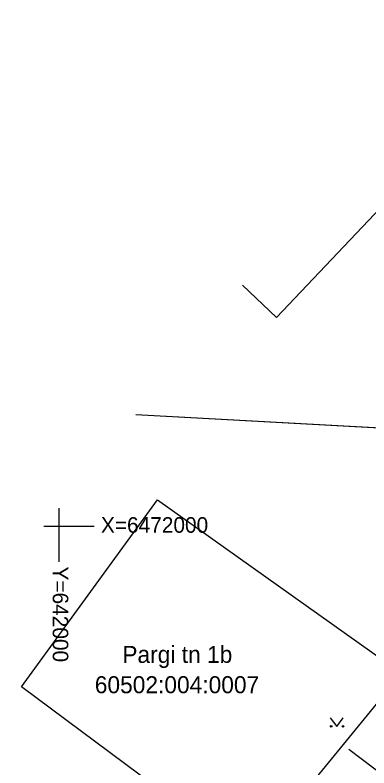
# Model space of a CAD drawing. Extents: x 641898 to 642452, y 6471715 to 6472255.
# Drawn here: x 641996.9 to 642021.9, y 6471983 to 6472036.1 of the extents above; entities that cross this region are included whole.
import ezdxf

# ---------------------------------------------------------------- set-up
doc = ezdxf.new("R2010")
doc.units = 0
for name, color, linetype in [('HALJASTUS', 7, 'Continuous'), ('HOONE', 7, 'Continuous'), ('MOOTPIIR', 7, 'Continuous'), ('MPOHULIIN', 7, 'Continuous'), ('PIIR', 7, 'Continuous'), ('SIOHULIIN', 7, 'Continuous'), ('VORK', 7, 'Continuous')]:
    doc.layers.add(name, color=color, linetype=linetype)

msp = doc.modelspace()

# ---------------------------------------------------------------- linework, layer by layer
at = {"layer": 'HALJASTUS'}
for p, q in [((642019.157, 6471986.488), (642019.621, 6471985.882)), ((642019.621, 6471985.882), (642020.066, 6471986.488))]:
    msp.add_line(p, q, dxfattribs=at)
for centre in [(642019.22, 6471985.882), (642020.049, 6471985.882)]:
    msp.add_circle(centre, 0.055, dxfattribs=at)
at = {"layer": 'HOONE'}
msp.add_lwpolyline([(642020.456, 6471984.276), (642023.066, 6471982.309), (642019.558, 6471977.655), (642016.948, 6471979.622)], dxfattribs=at)
at = {"layer": 'MOOTPIIR'}
msp.add_lwpolyline([(642057.038, 6472006.154), (641981.622, 6471911.832), (641974.173, 6471900.785), (641991.385, 6471889.279), (641976.334, 6471874.678), (641962.442, 6471882.56), (641955.727, 6471896.847), (641967.922, 6471920.935), (642044.157, 6472013.993), (642057.02, 6472034.672), (642071.202, 6472024.941)], close=True, dxfattribs=at)
at = {"layer": 'MPOHULIIN'}
msp.add_line((642023.51, 6472006.876), (642005.441, 6472007.868), dxfattribs=at)
at = {"layer": 'PIIR'}
for p, q in [((642043.28, 6472044.21), (642015.37, 6472014.73)), ((642015.37, 6472014.73), (642012.968, 6472016.994)), ((641997.37, 6471988.68), (642006.96, 6472001.86)), ((642006.96, 6472001.86), (642027.1, 6471987.54)), ((642017.35, 6471973.82), (641997.37, 6471988.68))]:
    msp.add_line(p, q, dxfattribs=at)
at = {"layer": 'SIOHULIIN'}
msp.add_lwpolyline([(642023.51, 6472006.876), (642005.441, 6472007.868)], dxfattribs=at)
at = {"layer": 'VORK'}
for p, q in [((642000, 6472001.271), (642000, 6471997.5)), ((641998.952, 6472000), (642002.5, 6472000))]:
    msp.add_line(p, q, dxfattribs=at)

# ---------------------------------------------------------------- texts
at = {"layer": 'PIIR'}
for s, p in [('Pargi tn 1b', (642004.483, 6471990.361)), ('60502:004:0007', (642002.54, 6471988.225))]:
    msp.add_text(s, height=1.2, dxfattribs=at).set_placement(p)
at = {"layer": 'VORK'}
msp.add_text('X=6472000', height=1.1, dxfattribs=at).set_placement((642002.975, 6471999.542))
msp.add_text('Y=642000', height=1.1, rotation=270, dxfattribs=at).set_placement((641999.571, 6471997.165))

doc.saveas('drawing.dxf')
